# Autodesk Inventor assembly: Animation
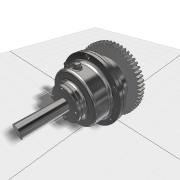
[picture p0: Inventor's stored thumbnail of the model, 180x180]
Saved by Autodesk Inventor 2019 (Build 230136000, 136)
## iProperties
Created: 2019-01
Part Number: Animation
Document SubType Name: Assembly
Designer: m.vorobev
Author: m.vorobev
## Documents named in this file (2)
- C:\Users\m.vorobev.TRINITY\Documents\Inventor\00-000.06.21.21.00\Animation.iam
- C:\Users\m.vorobev.TRINITY\Documents\Inventor\00-000.06.21.21.00\Animation-01.iam
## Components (1 placed, 1 different names)
1. Animation-01:1 [sub-assembly] — Flush:1, Rotating-01, Mate:1
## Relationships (3: Flush 1, Angle 1, Mate 1)
- Flush:1: Animation-01:1
- Rotating-01 [Angle]: Animation-01:1
- Mate:1: Animation-01:1
